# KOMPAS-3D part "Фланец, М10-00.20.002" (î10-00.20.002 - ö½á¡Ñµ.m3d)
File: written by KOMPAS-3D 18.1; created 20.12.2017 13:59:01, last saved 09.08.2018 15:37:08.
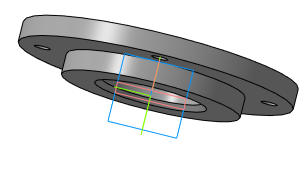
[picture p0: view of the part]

Document properties: Автор: Мирончук; Организация: Мирончук; Полное имя файла: D:\Magna\Магна Ins\Магна ins 10\М10-00.00.000\3Д\М10-00.20.002 - Фланец.m3d

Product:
- Part/product: Фланец  | designation М10-00.20.002
    Материал: Полипропилен  ГОСТ 26996-86 (density 900 kg/m3)
    Масса: 0.439491
    Раздел спецификации: Детали
    Форматы листов документа: A3
    Примечание: габ. 71, 80
    source file: М10-00.20.002 - Фланец.cdw

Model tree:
1. Эскиз:1
2. Операция вращения:1
     Угол 1 = 360
3. Эскиз:2  (with: Операция вращения:1)
4. Вырезать элемент выдавливания:1
     Расстояние 1 = 30
5. Массив по концентрической сетке:1  (with: Вырезать элемент выдавливания:1, Эскиз:2, Операция вращения:1)  (4 pattern instances)
     Шаг 2 = 360
6. Фаска:1  (with: Операция вращения:1)  (labels: Полипропилен  ГОСТ 26996-86)
     Угол = 45; Длина 1 = 4; Длина 2 = 4

Expressions: 130/2; 73.8/2
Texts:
  Body Specification ( left align )
  Body Specificaton ( centered )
